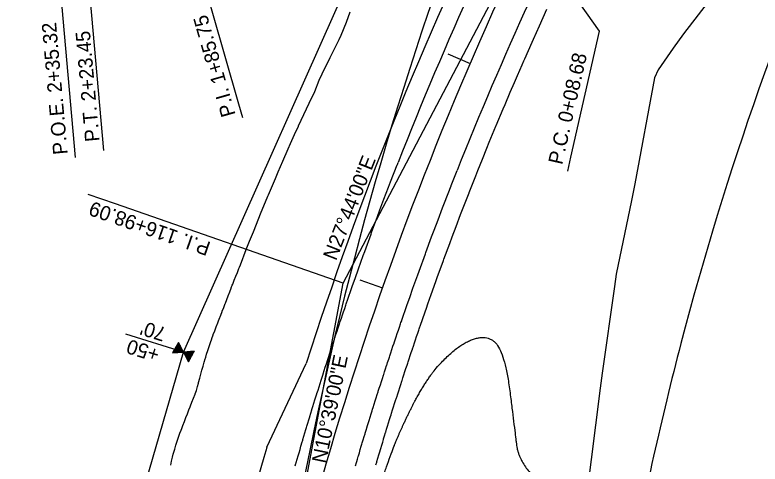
# Model space of a CAD drawing. Extents: x 674098 to 689971, y 764717 to 781049.
# Drawn here: x 688639.1 to 688948.3, y 766697.2 to 766883.6 of the extents above; entities that cross this region are included whole.
import ezdxf

# ---------------------------------------------------------------- set-up
doc = ezdxf.new("R2010")
doc.units = 0
for name, color, linetype in [('FLOODPLAIN', 7, 'Continuous'), ('R_Fence', 7, 'Continuous'), ('R_Horz Alg', 7, 'Continuous'), ('R_Horz Alg Annot', 7, 'Continuous'), ('R_Horz Alg Station', 7, 'Continuous'), ('R_Horz Alg Station Annot', 7, 'Continuous'), ('R_Proposed Const Limits', 7, 'Continuous'), ('R_Proposed Const Limits Stage 2', 7, 'Continuous'), ('R_Proposed Road', 7, 'Continuous'), ('R_Proposed Road S2', 7, 'Continuous'), ('R_Proposed Shoulder S1', 7, 'Continuous'), ('R_Proposed Shoulder S2', 7, 'Continuous'), ('R_ROW', 7, 'Continuous'), ('R_ROW Annot', 7, 'Continuous'), ('S_EXIST_ROW', 7, 'Continuous')]:
    doc.layers.add(name, color=color, linetype=linetype)

msp = doc.modelspace()

# ---------------------------------------------------------------- linework, layer by layer
at = {"layer": 'FLOODPLAIN'}
msp.add_open_spline([(688557.23, 766766.05), (688591.58, 766711.04), (688595.35, 766687.04), (688608.48, 766656.15), (688627.02, 766628.3), (688632.82, 766586.19), (688639.4, 766524.53), (688653.57, 766501.98), (688669.3, 766485), (688687.59, 766474.45), (688723.13, 766481.9), (688739.6, 766509.51), (688789, 766687.63), (688806.98, 766729.19), (688822.47, 766746.61), (688835.88, 766751.3), (688842.63, 766741.88), (688846.4, 766712.12), (688847.97, 766698.77), (688859.62, 766686.41), (688884.96, 766674.2), (688946.59, 766675.74), (689003.92, 766689.73), (689113.2, 766693.11), (689155.64, 766709.56), (689222.69, 766748.31), (689278.94, 766804.47), (689325.37, 766856.38), (689397.34, 766962.93), (689435.45, 766991.81), (689488.41, 767032.29), (689550.62, 767060.41), (689676.67, 767118.63), (689783.6, 767157.05), (689856.65, 767174.65), (689971.45, 767193.2)], degree=2, dxfattribs=at)
at = {"layer": 'R_Fence'}
for p, q in [((688705.83, 766745.57), (688706.41, 766743.47)), ((688706.17, 766746.18), (688706.92, 766743.51)), ((688706.52, 766746.8), (688707.43, 766743.55)), ((688706.87, 766747.42), (688707.93, 766743.59)), ((688707.66, 766746.44), (688708.44, 766743.63)), ((688704.78, 766743.72), (688704.88, 766743.36)), ((688705.13, 766744.34), (688705.39, 766743.4)), ((688705.48, 766744.95), (688705.9, 766743.44)), ((688708.81, 766744.16), (688708.95, 766743.66)), ((688709.46, 766743.7), (688709.96, 766741.89)), ((688709.97, 766743.74), (688711.1, 766739.66)), ((688710.48, 766743.78), (688711.45, 766740.28)), ((688710.99, 766743.81), (688711.8, 766740.89)), ((688711.49, 766743.85), (688712.15, 766741.51)), ((688712, 766743.89), (688712.49, 766742.12)), ((688712.51, 766743.93), (688712.84, 766742.74)), ((688713.02, 766743.96), (688713.19, 766743.36)), ((688713.53, 766744), (688713.54, 766743.97))]:
    msp.add_line(p, q, dxfattribs=at)
msp.add_lwpolyline([(688709.07, 766743.67), (688709.06, 766743.68), (688707.02, 766747.69), (688704.57, 766743.34), (688709.05, 766743.67), (688709.06, 766743.66), (688711.1, 766739.65), (688713.56, 766744), (688709.07, 766743.67)], dxfattribs=at)
at = {"layer": 'R_Horz Alg'}
for p, q in [((688775.27, 766772.26), (688875.39, 766962.69)), ((688735.51, 766560.83), (688775.27, 766772.26))]:
    msp.add_line(p, q, dxfattribs=at)
msp.add_arc((690143.23, 766296.11), 1432.39, 152.26653, 169.35, dxfattribs=at)
msp.add_arc((690143.23, 766296.11), 1432.39, 152.26653, 169.35, dxfattribs=at)
at = {"layer": 'R_Horz Alg Station'}
for points in [[(688873.26, 766977.18), (688857.64, 766910.67), (688881.48, 766876.86), (688869.65, 766824.53), (688868.33, 766818.68)], [(688704.41, 766942.87), (688731.96, 766846.74), (688733.61, 766840.97)], [(688654.1, 766938.42), (688664.18, 766824.36)], [(688665.92, 766939.46), (688675.84, 766827.29)], [(688818.79, 766867.38), (688827.97, 766863.42)], [(688775.27, 766772.26), (688680.83, 766805.14), (688669.5, 766809.08)], [(688782.17, 766773.6), (688791.6, 766770.29)]]:
    msp.add_lwpolyline(points, dxfattribs=at)
at = {"layer": 'R_Proposed Const Limits'}
msp.add_lwpolyline([(688703.76, 766696.69), (688704.11, 766698.38), (688704.5, 766700.07), (688704.85, 766701.29), (688704.98, 766701.73), (688705.47, 766703.39), (688705.62, 766703.89), (688705.96, 766705.05), (688706.45, 766706.71), (688706.99, 766708.35), (688707.61, 766709.97), (688708.08, 766711.21), (688708.17, 766711.44), (688708.23, 766711.59), (688708.85, 766713.21), (688709.47, 766714.83), (688710.09, 766716.45), (688710.72, 766718.07), (688711.03, 766718.88), (688711.34, 766719.68), (688711.85, 766720.97), (688711.97, 766721.3), (688712.6, 766722.91), (688713.23, 766724.53), (688713.86, 766726.14), (688713.93, 766726.31), (688714.45, 766727.77), (688714.9, 766729.44), (688715.29, 766730.82), (688715.36, 766731.1), (688715.82, 766732.77), (688716.15, 766733.95), (688716.29, 766734.43), (688716.75, 766736.1), (688717.22, 766737.76), (688717.69, 766739.42), (688718.09, 766740.86), (688718.16, 766741.08), (688718.33, 766741.59), (688718.69, 766742.73), (688719.21, 766744.38), (688719.73, 766746.02), (688720.26, 766747.67), (688720.78, 766749.15), (688720.84, 766749.3), (688721.38, 766750.76), (688721.44, 766750.92), (688722.04, 766752.54), (688722.65, 766754.16), (688723.26, 766755.78), (688723.57, 766756.61), (688723.86, 766757.39), (688724.5, 766759), (688725.11, 766760.5), (688725.15, 766760.61), (688725.8, 766762.21), (688726.41, 766763.83), (688726.48, 766764.01), (688727.03, 766765.44), (688727.64, 766767.06), (688728.26, 766768.67), (688728.85, 766770.23), (688728.87, 766770.29), (688729.32, 766771.44), (688729.49, 766771.9), (688730.15, 766773.5), (688730.81, 766775.1), (688731.44, 766776.71), (688732.06, 766778.32), (688732.26, 766778.83), (688732.68, 766779.93), (688735.14, 766786.23), (688736.48, 766789.63), (688738.06, 766793.62), (688740.33, 766799.3), (688741.03, 766800.99), (688744.1, 766808.31), (688744.35, 766808.91), (688747.19, 766815.63), (688748.42, 766818.5), (688750.31, 766822.92), (688752.52, 766828.06), (688753.45, 766830.21), (688755.09, 766833.96), (688756.75, 766837.44), (688756.8, 766837.55), (688760.17, 766844.6), (688761.27, 766846.95), (688763.53, 766851.79), (688765.43, 766856.47), (688766.59, 766859.09), (688769.93, 766865.85), (688770.11, 766866.21), (688773.63, 766873.32), (688774.46, 766875.2), (688776.66, 766880.63), (688778.21, 766884.88)], dxfattribs=at)
at = {"layer": 'R_Proposed Const Limits Stage 2'}
msp.add_lwpolyline([(688964.61, 766933.45), (688971.86, 766928.87), (688969.15, 766924.65), (688963.21, 766916.51), (688963.19, 766916.49), (688957.31, 766911.58), (688941.2, 766903.78), (688934.78, 766899.47), (688916.53, 766875.79), (688912.2, 766869.83), (688905.96, 766860.8), (688904.46, 766857.46), (688896.27, 766813.43), (688894.91, 766806.62), (688888.63, 766776), (688887.87, 766770.9), (688882.72, 766734.86), (688881.93, 766728.74), (688876.21, 766683.7)], dxfattribs=at)
at = {"layer": 'R_Proposed Road'}
for points in [[(688755.43, 766696.44), (688755.71, 766697.43), (688755.78, 766697.66), (688755.82, 766697.81), (688756.22, 766699.18), (688756.62, 766700.55), (688757.02, 766701.92), (688757.42, 766703.29), (688757.82, 766704.66), (688757.94, 766705.04), (688758.23, 766706.03), (688758.55, 766707.11), (688758.63, 766707.4), (688759.04, 766708.76), (688759.45, 766710.13), (688759.86, 766711.5), (688760.13, 766712.41), (688760.27, 766712.86), (688760.68, 766714.23), (688761.1, 766715.59), (688761.45, 766716.77), (688761.51, 766716.96), (688761.93, 766718.32), (688762.34, 766719.69), (688762.37, 766719.77), (688762.76, 766721.05), (688763.18, 766722.42), (688763.61, 766723.78), (688764.03, 766725.14), (688764.42, 766726.4), (688764.45, 766726.51), (688764.64, 766727.11), (688764.88, 766727.87), (688765.31, 766729.23), (688765.74, 766730.59), (688766.17, 766731.95), (688766.6, 766733.31), (688766.96, 766734.45), (688767.03, 766734.67), (688767.46, 766736.02), (688767.46, 766736.03), (688767.9, 766737.39), (688768.34, 766738.75), (688768.77, 766740.11), (688769.21, 766741.46), (688769.31, 766741.77), (688769.65, 766742.82), (688770.1, 766744.18), (688770.54, 766745.53), (688770.57, 766745.61), (688770.98, 766746.89), (688771.43, 766748.24), (688771.7, 766749.08), (688771.88, 766749.6), (688772.33, 766750.95), (688772.78, 766752.31), (688773.23, 766753.66), (688773.68, 766755.01), (688773.74, 766755.19), (688774.13, 766756.37), (688774.14, 766756.37), (688774.59, 766757.72), (688775.05, 766759.07), (688775.5, 766760.42), (688775.96, 766761.77), (688776.42, 766763.12), (688776.61, 766763.66), (688776.89, 766764.47), (688776.98, 766764.74), (688779.11, 766770.92), (688779.64, 766772.45), (688780.28, 766774.26), (688781.66, 766778.18), (688783.65, 766783.77), (688784.25, 766785.43), (688786.87, 766792.65), (688787.09, 766793.25), (688789.53, 766799.87), (688790.59, 766802.7), (688792.24, 766807.07), (688794.16, 766812.13), (688794.98, 766814.26), (688797.75, 766821.42), (688797.8, 766821.54), (688798.12, 766822.35)], [(688780.45, 766696.52), (688780.84, 766697.87), (688780.95, 766698.24), (688781.24, 766699.22), (688781.56, 766700.28), (688781.64, 766700.56), (688782.04, 766701.91), (688782.44, 766703.25), (688782.84, 766704.59), (688783.11, 766705.49), (688783.25, 766705.94), (688783.65, 766707.28), (688784.06, 766708.62), (688784.41, 766709.78), (688784.47, 766709.97), (688784.88, 766711.31), (688785.29, 766712.65), (688785.31, 766712.73), (688785.7, 766713.99), (688786.12, 766715.33), (688786.53, 766716.67), (688786.95, 766718.01), (688787.33, 766719.26), (688787.36, 766719.35), (688787.55, 766719.95), (688787.78, 766720.69), (688788.2, 766722.03), (688788.62, 766723.37), (688789.05, 766724.71), (688789.47, 766726.05), (688789.83, 766727.16), (688789.9, 766727.38), (688790.32, 766728.71), (688790.32, 766728.72), (688790.75, 766730.06), (688791.18, 766731.39), (688791.61, 766732.73), (688792.04, 766734.06), (688792.14, 766734.36), (688792.48, 766735.4), (688792.91, 766736.73), (688793.35, 766738.07), (688793.37, 766738.15), (688793.78, 766739.4), (688794.22, 766740.73), (688794.49, 766741.55), (688794.66, 766742.06), (688795.1, 766743.4), (688795.55, 766744.73), (688795.99, 766746.06), (688796.44, 766747.39), (688796.49, 766747.56), (688796.88, 766748.72), (688796.88, 766748.73), (688797.33, 766750.05), (688797.78, 766751.38), (688798.23, 766752.71), (688798.68, 766754.04), (688799.13, 766755.37), (688799.31, 766755.89), (688799.59, 766756.69), (688799.68, 766756.95), (688801.78, 766763.04), (688802.3, 766764.53), (688802.93, 766766.32), (688804.29, 766770.17), (688806.24, 766775.66), (688806.83, 766777.29), (688809.41, 766784.41), (688809.62, 766784.98), (688812.03, 766791.5), (688813.07, 766794.28), (688814.68, 766798.58), (688816.58, 766803.56), (688817.38, 766805.64), (688820.11, 766812.7), (688820.15, 766812.81), (688822.58, 766818.96)]]:
    msp.add_lwpolyline(points, dxfattribs=at)
msp.add_arc((690143.23, 766296.11), 1444.39, 152.26653, 158.63342, dxfattribs=at)
at = {"layer": 'R_Proposed Road S2'}
msp.add_arc((690143.23, 766296.11), 1420.39, 152.26653, 158.40118, dxfattribs=at)
at = {"layer": 'R_Proposed Shoulder S1'}
msp.add_line((688743.6, 766704.14), (688760, 766738.95), dxfattribs=at)
msp.add_lwpolyline([(688788.91, 766696.94), (688789.22, 766698.01), (688789.31, 766698.28), (688789.7, 766699.62), (688790.1, 766700.96), (688790.5, 766702.29), (688790.77, 766703.19), (688790.91, 766703.63), (688791.31, 766704.97), (688791.71, 766706.3), (688792.06, 766707.45), (688792.12, 766707.64), (688792.53, 766708.97), (688792.94, 766710.31), (688792.96, 766710.38), (688793.35, 766711.64), (688793.76, 766712.97), (688794.17, 766714.3), (688794.58, 766715.64), (688794.97, 766716.87), (688795, 766716.97), (688795.18, 766717.56), (688795.41, 766718.3), (688795.83, 766719.63), (688796.25, 766720.96), (688796.67, 766722.29), (688797.09, 766723.62), (688797.45, 766724.74), (688797.52, 766724.95)], dxfattribs=at)
for radius, start, end in [(1452.39, 153.8156, 162.24747), (1457.89, 163.74725, 169.35)]:
    msp.add_arc((690143.23, 766296.11), radius, start, end, dxfattribs=at)
at = {"layer": 'R_Proposed Shoulder S2'}
msp.add_lwpolyline([(688797.52, 766724.95), (688797.94, 766726.27), (688797.94, 766726.28), (688798.37, 766727.61), (688798.79, 766728.94), (688799.22, 766730.27), (688799.65, 766731.6), (688799.75, 766731.89), (688800.08, 766732.92), (688800.51, 766734.25), (688800.95, 766735.58), (688800.97, 766735.65), (688801.38, 766736.9), (688801.82, 766738.23), (688802.09, 766739.04), (688802.26, 766739.55), (688802.7, 766740.88), (688803.14, 766742.2), (688803.58, 766743.52), (688804.02, 766744.85), (688804.08, 766745.01), (688804.46, 766746.17), (688804.46, 766746.18), (688804.91, 766747.49), (688805.36, 766748.81), (688805.8, 766750.14), (688806.25, 766751.46), (688806.7, 766752.78), (688806.88, 766753.3), (688807.15, 766754.1), (688807.24, 766754.35), (688809.33, 766760.41), (688809.85, 766761.89), (688810.47, 766763.67), (688811.82, 766767.5), (688813.77, 766772.96), (688814.35, 766774.58), (688816.92, 766781.65), (688817.13, 766782.23), (688819.52, 766788.71), (688820.56, 766791.48), (688822.16, 766795.75), (688824.05, 766800.7), (688824.84, 766802.77), (688827.56, 766809.79), (688827.6, 766809.89), (688830.31, 766816.79), (688831.22, 766819.07), (688833.1, 766823.77), (688834.91, 766828.22), (688835.93, 766830.73), (688838.65, 766837.34), (688838.8, 766837.69), (688841.7, 766844.63), (688842.46, 766846.43), (688844.64, 766851.55), (688846.34, 766855.5), (688847.61, 766858.45), (688849.56, 766862.91), (688850.27, 766864.54), (688850.63, 766865.34), (688853.68, 766872.22), (688854.27, 766873.55), (688856.76, 766879.08), (688858.34, 766882.54), (688859.88, 766885.92)], dxfattribs=at)
at = {"layer": 'R_ROW'}
msp.add_lwpolyline([(688665.23, 766592.3), (688709.06, 766743.68), (688790.56, 766926.6)], dxfattribs=at)
at = {"layer": 'R_ROW Annot'}
msp.add_lwpolyline([(688709.06, 766743.68), (688685.19, 766751.13)], dxfattribs=at)
at = {"layer": 'S_EXIST_ROW'}
for radius, start, end in [(1332.39, 155.84367, 165.34172), (1472.39, 159.28665, 169.48718), (1332.39, 165.34172, 169.48718)]:
    msp.add_arc((690204.47, 766410.11), radius, start, end, dxfattribs=at)

# ---------------------------------------------------------------- texts
at = {"layer": 'R_Horz Alg Annot'}
for s, rotation, p in [('N27%%d44\'00"E', 68.5495, (688772.34, 766781.31)), ('N10%%d39\'00"E', 78.3363, (688768.12, 766697.21))]:
    msp.add_text(s, height=6, rotation=rotation, dxfattribs=at).set_placement(p)
at = {"layer": 'R_Horz Alg Station Annot'}
for s, rotation, p in [('P.I. 1+85.75', 105.9882, (688730.74, 766842.22)), ('P.O.E. 2+35.32', 95.0527, (688661.05, 766825.84)), ('P.T. 2+23.45', 95.0527, (688674.28, 766831.19)), ('P.C. 0+08.68', 77.2665, (688866.16, 766821.14)), ('P.I. 116+98.09', 160.8083, (688720.76, 766789.12))]:
    msp.add_text(s, height=6, rotation=rotation, dxfattribs=at).set_placement(p)
at = {"layer": 'R_ROW Annot'}
for s, p in [("70'", (688702.35, 766753.65)), ('+50', (688699.67, 766745.05))]:
    msp.add_text(s, height=6, rotation=162.668, dxfattribs=at).set_placement(p)

doc.saveas('drawing.dxf')
